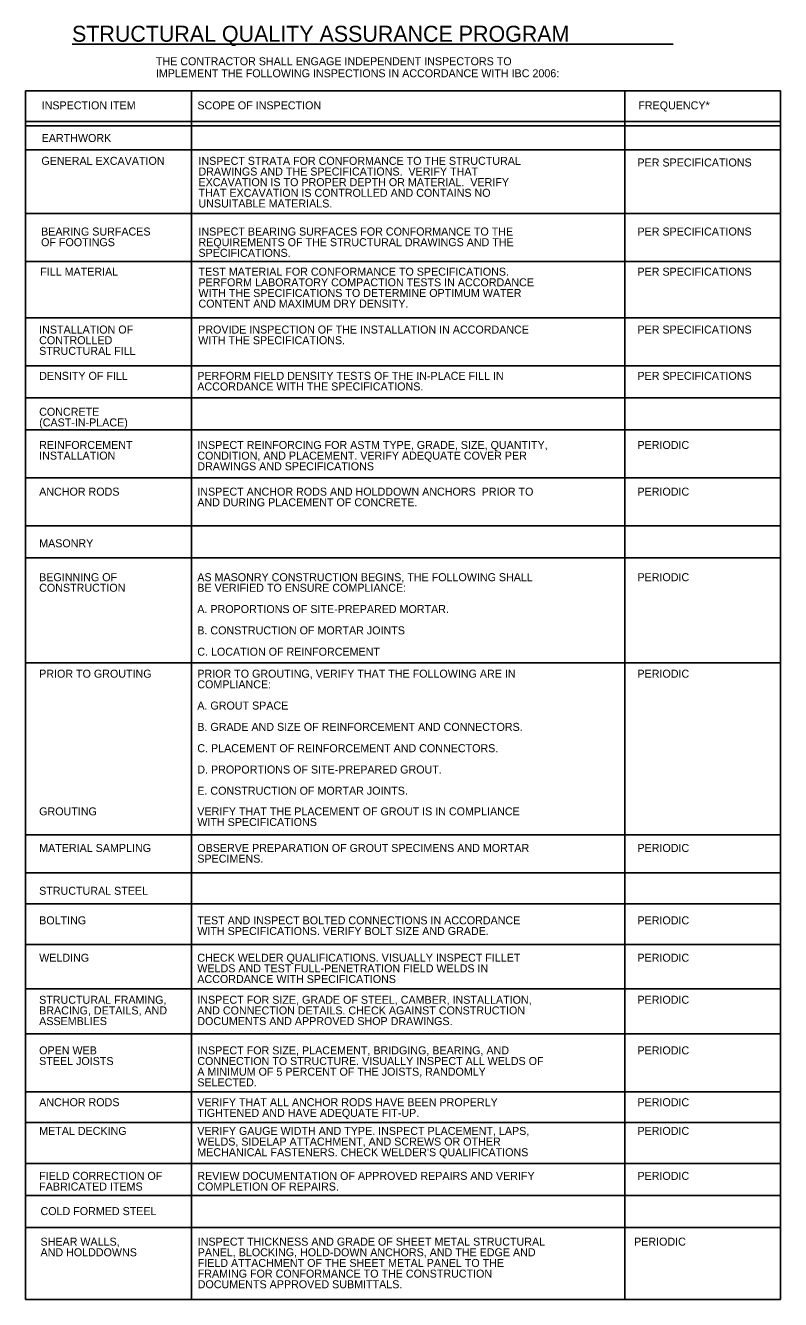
# Model space of a CAD drawing. Extents: x 2632118 to 2632142.4, y 1706724.1 to 1706788.4.
# Drawn here: x 2632118.05 to 2632125.9, y 1706724.93 to 1706738.2 of the extents above; entities that cross this region are included whole.
import ezdxf

# ---------------------------------------------------------------- set-up
doc = ezdxf.new("R2010")
doc.units = 0
doc.layers.add('S-ANNO-TEXT', color=7, linetype='Continuous')

msp = doc.modelspace()

# ---------------------------------------------------------------- linework, layer by layer
at = {"layer": 'S-ANNO-TEXT'}
for p, q in [((2632118.531, 1706738.005), (2632124.789, 1706738.005)), ((2632118.047, 1706737.521), (2632125.905, 1706737.521)), ((2632118.047, 1706724.932), (2632118.047, 1706737.521)), ((2632119.775, 1706737.521), (2632119.775, 1706724.932)), ((2632124.285, 1706737.521), (2632124.285, 1706724.932)), ((2632125.905, 1706737.521), (2632125.905, 1706724.932)), ((2632118.047, 1706737.201), (2632125.893, 1706737.201)), ((2632118.047, 1706737.157), (2632125.905, 1706737.157)), ((2632118.047, 1706736.907), (2632125.905, 1706736.907)), ((2632118.047, 1706736.241), (2632125.905, 1706736.241)), ((2632118.047, 1706735.741), (2632125.905, 1706735.741)), ((2632118.047, 1706735.157), (2632125.905, 1706735.157)), ((2632118.047, 1706734.657), (2632125.905, 1706734.657)), ((2632118.047, 1706734.324), (2632125.905, 1706734.324)), ((2632118.047, 1706733.991), (2632125.905, 1706733.991)), ((2632118.047, 1706733.491), (2632125.905, 1706733.491)), ((2632118.047, 1706732.991), (2632125.905, 1706732.991)), ((2632118.047, 1706732.657), (2632125.905, 1706732.657)), ((2632118.047, 1706731.562), (2632125.905, 1706731.562)), ((2632118.047, 1706729.773), (2632125.905, 1706729.773)), ((2632118.047, 1706729.377), (2632125.905, 1706729.377)), ((2632118.047, 1706729.053), (2632125.905, 1706729.053)), ((2632118.047, 1706728.63), (2632125.905, 1706728.63)), ((2632118.047, 1706728.168), (2632125.905, 1706728.168)), ((2632118.047, 1706727.698), (2632125.905, 1706727.698)), ((2632118.047, 1706727.094), (2632125.905, 1706727.094)), ((2632118.047, 1706726.777), (2632125.905, 1706726.777)), ((2632118.047, 1706726.348), (2632125.905, 1706726.348)), ((2632118.047, 1706726.015), (2632125.905, 1706726.015)), ((2632118.047, 1706725.682), (2632125.905, 1706725.682)), ((2632118.047, 1706725.682), (2632125.905, 1706725.682)), ((2632125.905, 1706724.932), (2632118.047, 1706724.932))]:
    msp.add_line(p, q, dxfattribs=at)

# ---------------------------------------------------------------- texts
for s, height, p in [('STRUCTURAL QUALITY ASSURANCE PROGRAM', 0.16667, (2632118.531, 1706738.031)), ('THE CONTRACTOR SHALL ENGAGE INDEPENDENT INSPECTORS TO', 0.08333, (2632119.404, 1706737.786)), ('IMPLEMENT THE FOLLOWING INSPECTIONS IN ACCORDANCE WITH IBC 2006:', 0.08333, (2632119.404, 1706737.661)), ('INSPECTION ITEM', 0.08333, (2632118.215, 1706737.327)), ('SCOPE OF INSPECTION', 0.08333, (2632119.836, 1706737.327)), ('FREQUENCY*', 0.0833, (2632124.425, 1706737.327)), ('EARTHWORK', 0.0833, (2632118.215, 1706736.987)), ('GENERAL EXCAVATION', 0.08333, (2632118.212, 1706736.749)), ('INSPECT STRATA FOR CONFORMANCE TO THE STRUCTURAL ', 0.08333, (2632119.847, 1706736.749)), ('DRAWINGS AND THE SPECIFICATIONS.  VERIFY THAT ', 0.08333, (2632119.847, 1706736.638)), ('PER SPECIFICATIONS', 0.08333, (2632124.416, 1706736.732)), ('EXCAVATION IS TO PROPER DEPTH OR MATERIAL.  VERIFY ', 0.08333, (2632119.847, 1706736.527)), ('THAT EXCAVATION IS CONTROLLED AND CONTAINS NO ', 0.08333, (2632119.847, 1706736.416)), ('UNSUITABLE MATERIALS.', 0.08333, (2632119.847, 1706736.305)), ('BEARING SURFACES', 0.08333, (2632118.209, 1706736.013)), ('INSPECT BEARING SURFACES FOR CONFORMANCE TO THE ', 0.08333, (2632119.847, 1706736.013)), ('PER SPECIFICATIONS', 0.08333, (2632124.416, 1706736.013)), ('OF FOOTINGS', 0.08333, (2632118.209, 1706735.902)), ('REQUIREMENTS OF THE STRUCTURAL DRAWINGS AND THE ', 0.08333, (2632119.847, 1706735.902)), ('SPECIFICATIONS.', 0.08333, (2632119.847, 1706735.791)), ('FILL MATERIAL', 0.08333, (2632118.2, 1706735.595)), ('TEST MATERIAL FOR CONFORMANCE TO SPECIFICATIONS.  ', 0.08333, (2632119.847, 1706735.595)), ('PER SPECIFICATIONS', 0.08333, (2632124.416, 1706735.595)), ('PERFORM LABORATORY COMPACTION TESTS IN ACCORDANCE ', 0.08333, (2632119.847, 1706735.484)), ('WITH THE SPECIFICATIONS TO DETERMINE OPTIMUM WATER ', 0.08333, (2632119.847, 1706735.373)), ('CONTENT AND MAXIMUM DRY DENSITY.', 0.08333, (2632119.847, 1706735.262)), ('INSTALLATION OF', 0.08333, (2632118.189, 1706734.992)), ('PROVIDE INSPECTION OF THE INSTALLATION IN ACCORDANCE ', 0.08333, (2632119.844, 1706734.992)), ('PER SPECIFICATIONS', 0.08333, (2632124.416, 1706734.992)), ('STRUCTURAL FILL', 0.08333, (2632118.189, 1706734.77)), ('CONTROLLED', 0.0833, (2632118.189, 1706734.881)), ('WITH THE SPECIFICATIONS.', 0.08333, (2632119.844, 1706734.881)), ('DENSITY OF FILL', 0.08333, (2632118.189, 1706734.51)), ('PERFORM FIELD DENSITY TESTS OF THE IN-PLACE FILL IN ', 0.08333, (2632119.835, 1706734.51)), ('PER SPECIFICATIONS', 0.08333, (2632124.416, 1706734.51)), ('ACCORDANCE WITH THE SPECIFICATIONS.', 0.08333, (2632119.835, 1706734.399)), ('CONCRETE', 0.0833, (2632118.189, 1706734.136)), ('(CAST-IN-PLACE)', 0.08333, (2632118.189, 1706734.025)), ('REINFORCEMENT', 0.08333, (2632118.189, 1706733.79)), ('INSPECT REINFORCING FOR ASTM TYPE, GRADE, SIZE, QUANTITY, ', 0.08333, (2632119.835, 1706733.79)), ('PERIODIC', 0.0833, (2632124.416, 1706733.79)), ('INSTALLATION', 0.08333, (2632118.189, 1706733.679)), ('CONDITION, AND PLACEMENT. VERIFY ADEQUATE COVER PER ', 0.08333, (2632119.835, 1706733.679)), ('DRAWINGS AND SPECIFICATIONS', 0.08333, (2632119.835, 1706733.568)), ('ANCHOR RODS', 0.08333, (2632118.189, 1706733.304)), ('INSPECT ANCHOR RODS AND HOLDDOWN ANCHORS  PRIOR TO ', 0.08333, (2632119.835, 1706733.304)), ('PERIODIC', 0.0833, (2632124.416, 1706733.304)), ('AND DURING PLACEMENT OF CONCRETE.', 0.08333, (2632119.835, 1706733.193)), ('MASONRY', 0.0833, (2632118.189, 1706732.766)), ('BEGINNING OF', 0.08333, (2632118.189, 1706732.413)), ('AS MASONRY CONSTRUCTION BEGINS, THE FOLLOWING SHALL ', 0.08333, (2632119.835, 1706732.413)), ('PERIODIC', 0.0833, (2632124.416, 1706732.413)), ('CONSTRUCTION', 0.08333, (2632118.189, 1706732.303)), ('BE VERIFIED TO ENSURE COMPLIANCE:', 0.08333, (2632119.835, 1706732.303)), ('A. PROPORTIONS OF SITE-PREPARED MORTAR. ', 0.08333, (2632119.835, 1706732.081)), ('B. CONSTRUCTION OF MORTAR JOINTS', 0.08333, (2632119.835, 1706731.859)), ('C. LOCATION OF REINFORCEMENT', 0.08333, (2632119.835, 1706731.637)), ('PRIOR TO GROUTING', 0.08333, (2632118.189, 1706731.408)), ('PRIOR TO GROUTING, VERIFY THAT THE FOLLOWING ARE IN ', 0.08333, (2632119.835, 1706731.408)), ('PERIODIC', 0.0833, (2632124.416, 1706731.408)), ('COMPLIANCE:', 0.08333, (2632119.835, 1706731.297)), ('A. GROUT SPACE', 0.08333, (2632119.835, 1706731.076)), ('B. GRADE AND SIZE OF REINFORCEMENT AND CONNECTORS.', 0.08333, (2632119.835, 1706730.854)), ('C. PLACEMENT OF REINFORCEMENT AND CONNECTORS.', 0.08333, (2632119.835, 1706730.632)), ('D. PROPORTIONS OF SITE-PREPARED GROUT. ', 0.08333, (2632119.835, 1706730.41)), ('E. CONSTRUCTION OF MORTAR JOINTS.', 0.08333, (2632119.835, 1706730.189)), ('GROUTING', 0.0833, (2632118.189, 1706729.974)), ('VERIFY THAT THE PLACEMENT OF GROUT IS IN COMPLIANCE ', 0.08333, (2632119.835, 1706729.974)), ('WITH SPECIFICATIONS', 0.08333, (2632119.835, 1706729.863)), ('MATERIAL SAMPLING', 0.08333, (2632118.189, 1706729.593)), ('OBSERVE PREPARATION OF GROUT SPECIMENS AND MORTAR', 0.08333, (2632119.835, 1706729.593)), ('PERIODIC', 0.0833, (2632124.416, 1706729.593)), ('SPECIMENS.', 0.0833, (2632119.835, 1706729.482)), ('STRUCTURAL STEEL', 0.08333, (2632118.189, 1706729.147)), ('BOLTING', 0.0833, (2632118.189, 1706728.839)), ('TEST AND INSPECT BOLTED CONNECTIONS IN ACCORDANCE ', 0.08333, (2632119.835, 1706728.839)), ('PERIODIC', 0.0833, (2632124.416, 1706728.839)), ('WITH SPECIFICATIONS. VERIFY BOLT SIZE AND GRADE.', 0.08333, (2632119.835, 1706728.728)), ('WELDING', 0.0833, (2632118.189, 1706728.45)), ('CHECK WELDER QUALIFICATIONS. VISUALLY INSPECT FILLET ', 0.08333, (2632119.835, 1706728.45)), ('PERIODIC', 0.0833, (2632124.416, 1706728.45)), ('WELDS AND TEST FULL-PENETRATION FIELD WELDS IN ', 0.08333, (2632119.835, 1706728.339)), ('ACCORDANCE WITH SPECIFICATIONS', 0.08333, (2632119.835, 1706728.228)), ('STRUCTURAL FRAMING, ', 0.08333, (2632118.189, 1706728.012)), ('INSPECT FOR SIZE, GRADE OF STEEL, CAMBER, INSTALLATION, ', 0.08333, (2632119.835, 1706728.012)), ('PERIODIC', 0.0833, (2632124.416, 1706728.012)), ('BRACING, DETAILS, AND', 0.08333, (2632118.189, 1706727.901)), ('AND CONNECTION DETAILS. CHECK AGAINST CONSTRUCTION ', 0.08333, (2632119.835, 1706727.901)), ('ASSEMBLIES', 0.0833, (2632118.189, 1706727.79)), ('DOCUMENTS AND APPROVED SHOP DRAWINGS.', 0.08333, (2632119.835, 1706727.79)), ('OPEN WEB', 0.0833, (2632118.189, 1706727.485)), ('INSPECT FOR SIZE, PLACEMENT, BRIDGING, BEARING, AND ', 0.08333, (2632119.835, 1706727.485)), ('PERIODIC', 0.0833, (2632124.416, 1706727.485)), ('STEEL JOISTS', 0.08333, (2632118.189, 1706727.374)), ('CONNECTION TO STRUCTURE. VISUALLY INSPECT ALL WELDS OF ', 0.08333, (2632119.835, 1706727.374)), ('A MINIMUM OF 5 PERCENT OF THE JOISTS, RANDOMLY ', 0.08333, (2632119.835, 1706727.263)), ('SELECTED.', 0.0833, (2632119.835, 1706727.152)), ('ANCHOR RODS ', 0.08333, (2632118.189, 1706726.945)), ('VERIFY THAT ALL ANCHOR RODS HAVE BEEN PROPERLY ', 0.08333, (2632119.835, 1706726.945)), ('PERIODIC', 0.0833, (2632124.416, 1706726.945)), ('TIGHTENED AND HAVE ADEQUATE FIT-UP.', 0.08333, (2632119.835, 1706726.834)), ('METAL DECKING ', 0.08333, (2632118.189, 1706726.646)), ('VERIFY GAUGE WIDTH AND TYPE. INSPECT PLACEMENT, LAPS, ', 0.08333, (2632119.835, 1706726.646)), ('WELDS, SIDELAP ATTACHMENT, AND SCREWS OR OTHER ', 0.08333, (2632119.835, 1706726.535)), ('PERIODIC', 0.0833, (2632124.416, 1706726.646)), ("MECHANICAL FASTENERS. CHECK WELDER'S QUALIFICATIONS", 0.08333, (2632119.835, 1706726.424)), ('FIELD CORRECTION OF', 0.08333, (2632118.189, 1706726.178)), ('REVIEW DOCUMENTATION OF APPROVED REPAIRS AND VERIFY ', 0.08333, (2632119.835, 1706726.178)), ('PERIODIC', 0.0833, (2632124.416, 1706726.178)), ('FABRICATED ITEMS', 0.08333, (2632118.189, 1706726.067)), ('COMPLETION OF REPAIRS.', 0.08333, (2632119.835, 1706726.067)), ('COLD FORMED STEEL', 0.08333, (2632118.203, 1706725.811)), ('SHEAR WALLS,', 0.08333, (2632118.203, 1706725.493)), ('INSPECT THICKNESS AND GRADE OF SHEET METAL STRUCTURAL ', 0.08333, (2632119.839, 1706725.493)), ('PERIODIC', 0.0833, (2632124.381, 1706725.493)), ('AND HOLDDOWNS', 0.08333, (2632118.203, 1706725.382)), ('PANEL, BLOCKING, HOLD-DOWN ANCHORS, AND THE EDGE AND ', 0.08333, (2632119.839, 1706725.382)), ('FIELD ATTACHMENT OF THE SHEET METAL PANEL TO THE ', 0.08333, (2632119.839, 1706725.271)), ('FRAMING FOR CONFORMANCE TO THE CONSTRUCTION ', 0.08333, (2632119.839, 1706725.16)), ('DOCUMENTS APPROVED SUBMITTALS.', 0.08333, (2632119.839, 1706725.049))]:
    msp.add_text(s, height=height, dxfattribs=at).set_placement(p)

doc.saveas('drawing.dxf')
